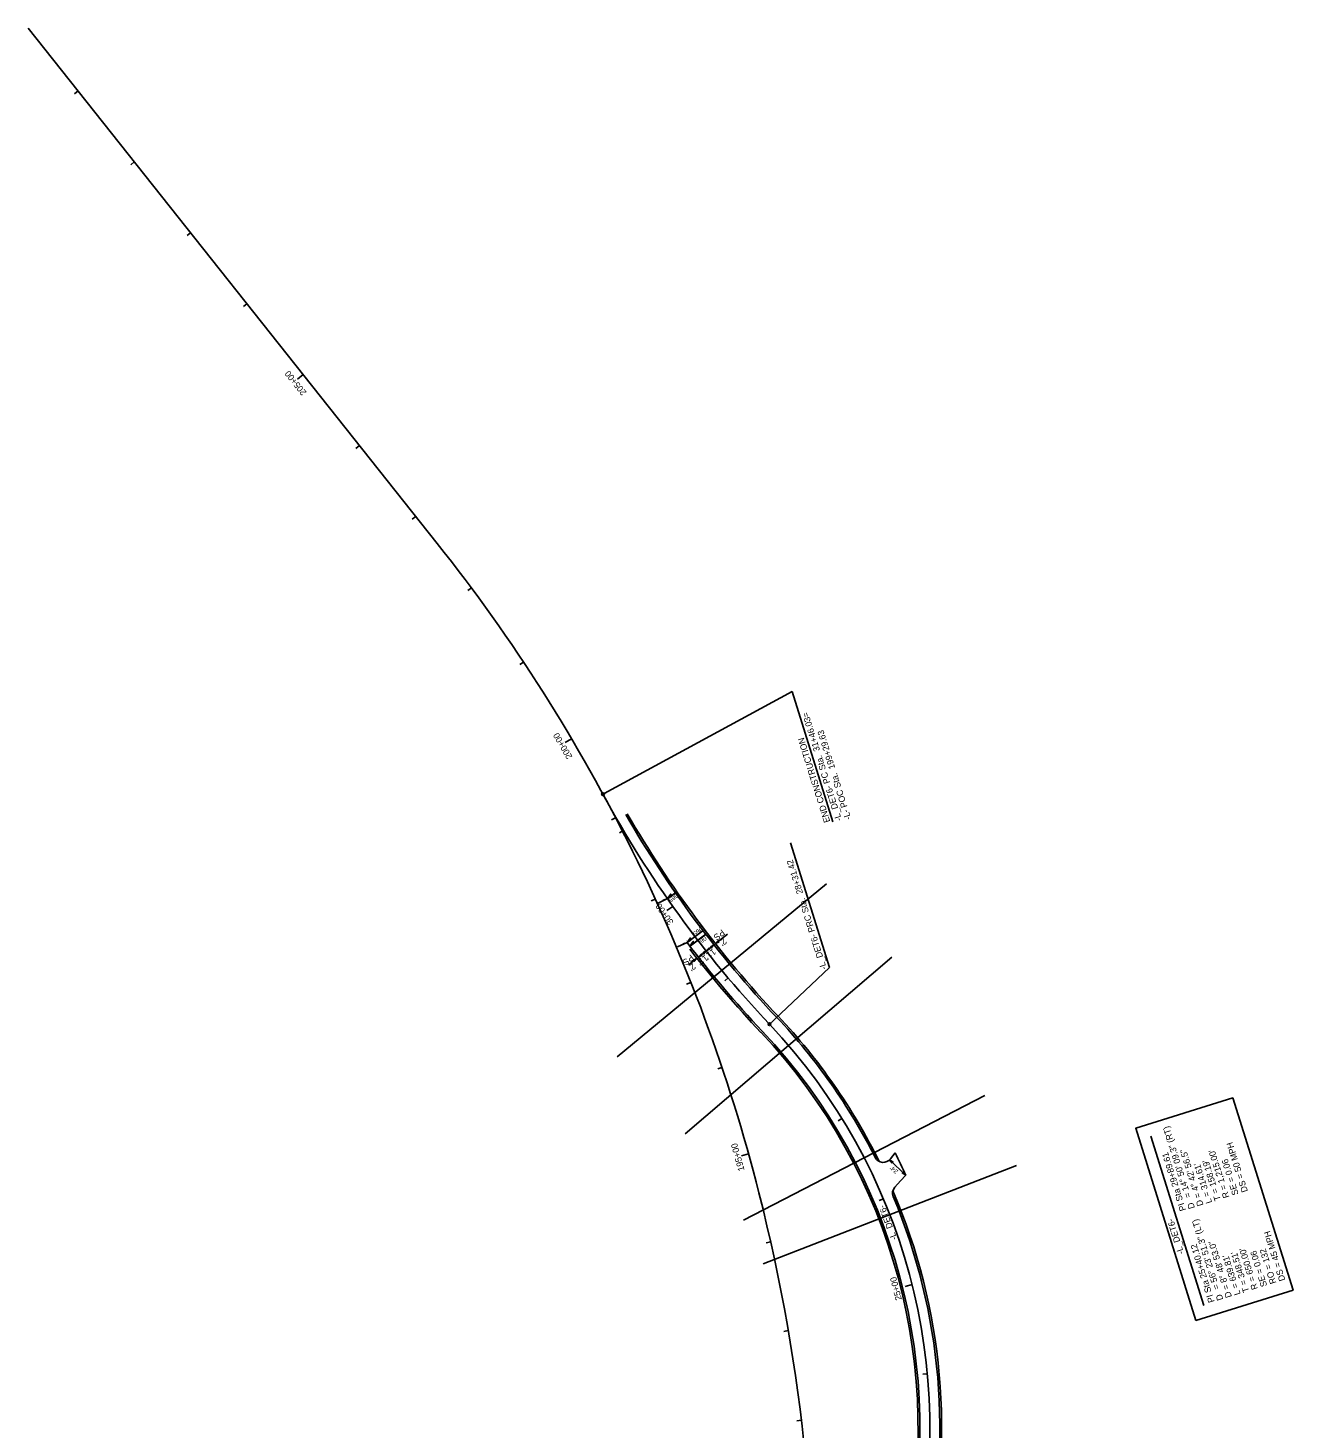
# Model space of a CAD drawing. Extents: x 473658 to 481584, y 489119 to 506230.
# Drawn here: x 473658 to 475055, y 504684 to 506230 of the extents above; entities that cross this region are included whole.
import ezdxf

# ---------------------------------------------------------------- set-up
doc = ezdxf.new("R2010")
doc.units = 0
for name, color, linetype in [('Exist Horizontal Alignment', 7, 'Continuous'), ('Prop Dimension', 7, 'Continuous'), ('Prop EOT', 7, 'Continuous'), ('Prop Grid Mask', 7, 'Continuous'), ('Prop Horizontal Alignment', 7, 'Continuous'), ('Prop Horizontal Alignment Curve and Spiral Data', 7, 'Continuous'), ('Prop Horizontal Alignment Station Label', 7, 'Continuous'), ('Prop Horizontal Alignment Tick Label', 7, 'Continuous'), ('Prop Horizontal Alignment Tick Large', 7, 'Continuous'), ('Prop Horizontal Alignment Tick Small', 7, 'Continuous'), ('Prop Paved Shoulder', 7, 'Continuous'), ('Prop Superelevation  Arrow CELL', 7, 'Continuous'), ('Prop Superelevation Label', 7, 'Continuous'), ('Scratch_Level_6', 7, 'Continuous')]:
    doc.layers.add(name, color=color, linetype=linetype)

msp = doc.modelspace()

# ---------------------------------------------------------------- linework, layer by layer
at = {"layer": 'Exist Horizontal Alignment'}
for points in [[(474611.9, 504976.5), (474609.2, 504980.2), (474613, 504977.6), (474612.1, 504977.4)], [(474624.2, 504966.7), (474626.9, 504963), (474623.1, 504965.5), (474624.1, 504965.7)]]:
    msp.add_lwpolyline(points, close=True, dxfattribs=at)
at = {"layer": 'Prop Dimension'}
for p, q in [((474430.1, 505229.2), (474416.9, 505218.8)), ((474415.3, 505217.5), (474398, 505203.9)), ((474396.5, 505202.7), (474387.2, 505195.4)), ((474626.9, 504963), (474609.2, 504980.2))]:
    msp.add_line(p, q, dxfattribs=at)
for points in [[(474410.7, 505212.9), (474406.7, 505210.7), (474409.7, 505214.1), (474409.8, 505213.2)], [(474411.3, 505215.3), (474415.3, 505217.5), (474412.3, 505214.1), (474412.2, 505215.1)], [(474420.9, 505220.9), (474416.9, 505218.8), (474419.9, 505222.2), (474420, 505221.2)], [(474392.5, 505200.5), (474396.5, 505202.7), (474393.4, 505199.2), (474393.4, 505200.2)], [(474402.1, 505206.1), (474398, 505203.9), (474401.1, 505207.3), (474401.1, 505206.3)], [(474402.7, 505208.5), (474406.7, 505210.7), (474403.6, 505207.3), (474403.6, 505208.3)]]:
    msp.add_lwpolyline(points, close=True, dxfattribs=at)
at = {"layer": 'Prop EOT'}
for p, q in [((474610.1, 504981.2), (474615.2, 504987.8)), ((474614.8, 504949.7), (474621, 504957)), ((474621, 504957), (474626.9, 504963))]:
    msp.add_line(p, q, dxfattribs=at)
for centre, radius, start, end in [((475360.5, 505963.2), 1204, 209.9929, 223.3134), ((475360.5, 505963.2), 1226, 217.3216, 223.3134), ((474003.6, 504683.9), 661, 26.8755, 43.3134), ((474003.6, 504683.9), 639, 346.9158, 43.3134), ((474602.1, 504987.2), 10, 206.8755, 322.9169), ((474003.6, 504683.9), 683, 24.1193, 26.4214), ((474622.4, 504943.2), 10, 139.5877, 202.7364), ((474003.6, 504683.9), 661, 346.9158, 22.7364)]:
    msp.add_arc(centre, radius, start, end, dxfattribs=at)
at = {"layer": 'Prop Grid Mask'}
msp.add_lwpolyline([(474947.5, 504802.7), (474881, 505015), (474988.1, 505048.5), (475054.7, 504836.2)], close=True, dxfattribs=at)
at = {"layer": 'Prop Horizontal Alignment'}
msp.add_line((474109.5, 505660.9), (473657.6, 506230), dxfattribs=at)
for centre, radius, start, end in [((472613.7, 504473.2), 1910, 14.2597, 38.4488), ((475360.5, 505963.2), 1215, 208.4775, 223.3134), ((474003.6, 504683.9), 650, 346.9158, 43.3134), ((472541, 504454.7), 1985, 356.9688, 14.2597)]:
    msp.add_arc(centre, radius, start, end, dxfattribs=at)
at = {"layer": 'Prop Horizontal Alignment Station Label'}
for p, q in [((474293.9, 505384.6), (474501.5, 505497.3)), ((474501.5, 505497.3), (474546.6, 505353.4)), ((474499.6, 505330.2), (474542.8, 505192.3)), ((474475.4, 505128.7), (474542.8, 505192.3)), ((474897.6, 505006.2), (474956.2, 504819.1))]:
    msp.add_line(p, q, dxfattribs=at)
for centre in [(474292.6, 505383.9), (474476.5, 505129.8)]:
    msp.add_circle(centre, 1.5, dxfattribs=at)
at = {"layer": 'Prop Horizontal Alignment Tick Large'}
for p, q in [((473961.5, 505847.2), (473955.3, 505842.2)), ((474257.9, 505445.1), (474251, 505441.1)), ((474369.7, 505260), (474363.2, 505255.4)), ((474453.4, 504986.5), (474445.7, 504984.3)), ((474634, 504842.2), (474626.2, 504840.3))]:
    msp.add_line(p, q, dxfattribs=at)
at = {"layer": 'Prop Horizontal Alignment Tick Small'}
for p, q in [((473712.8, 506160.5), (473708.9, 506157.4)), ((473775, 506082.2), (473771.1, 506079.1)), ((473837.2, 506003.9), (473833.3, 506000.7)), ((473899.3, 505925.5), (473895.4, 505922.4)), ((474023.7, 505768.9), (474019.8, 505765.8)), ((474085.9, 505690.6), (474082, 505687.5)), ((474147.3, 505611.7), (474143.3, 505608.7)), ((474204.8, 505529.8), (474200.6, 505527.1)), ((474306.5, 505357.7), (474302.1, 505355.4)), ((474315.3, 505343.9), (474311, 505341.3)), ((474350.5, 505267.9), (474345.9, 505265.9)), ((474430.9, 505181), (474427.1, 505177.7)), ((474389.7, 505176), (474385, 505174.1)), ((474497.5, 505106.4), (474493.7, 505103.1)), ((474424, 505082.1), (474419.3, 505080.5)), ((474556.4, 505025.7), (474552.2, 505023.1)), ((474602.3, 504936.9), (474597.7, 504935)), ((474477.8, 504889.5), (474472.9, 504888.4)), ((474497.2, 504791.4), (474492.3, 504790.6)), ((474650.8, 504743.7), (474645.8, 504743.3)), ((474511.7, 504692.5), (474506.7, 504691.9))]:
    msp.add_line(p, q, dxfattribs=at)
at = {"layer": 'Prop Paved Shoulder'}
for centre, radius, start, end in [((475360.5, 505963.2), 1202, 209.9929, 223.3134), ((475360.5, 505963.2), 1228, 217.6641, 223.3134), ((474003.6, 504683.9), 663, 26.3601, 43.3134), ((474003.6, 504683.9), 637, 346.9158, 43.3134), ((474003.6, 504683.9), 663, 346.9158, 23.2518)]:
    msp.add_arc(centre, radius, start, end, dxfattribs=at)
at = {"layer": 'Prop Superelevation  Arrow CELL'}
for points in [[(474363.8, 505268.5), (474367.5, 505273.6), (474367.6, 505271.1)], [(474385.6, 505219.9), (474389.1, 505225.1), (474389.3, 505222.7)], [(474388.6, 505215.9), (474392.2, 505221.2), (474392.3, 505218.7)]]:
    msp.add_lwpolyline(points, close=True, dxfattribs=at)
at = {"layer": 'Prop Superelevation Label'}
for p, q in [((474363.8, 505268.5), (474372.8, 505274.8)), ((474385.6, 505219.9), (474403.1, 505233.3)), ((474388.6, 505215.9), (474406.1, 505229.3))]:
    msp.add_line(p, q, dxfattribs=at)
at = {"layer": 'Scratch_Level_6'}
for p, q in [((474308.2, 505093.9), (474539.5, 505284.9)), ((474363.8, 505268.5), (474353.5, 505263.6)), ((474359.1, 505266.7), (474361.3, 505267.7)), ((474389.4, 505216.5), (474405.3, 505228.7)), ((474385.6, 505219.9), (474375, 505215.4)), ((474380.8, 505218.2), (474383, 505219.2)), ((474383.5, 505008.9), (474611.5, 505203.9)), ((474447.8, 504913.4), (474714.3, 505051)), ((474469.6, 504865), (474749.2, 504973.7))]:
    msp.add_line(p, q, dxfattribs=at)
for points in [[(474359.1, 505266.7), (474359.6, 505267.1), (474359.6, 505266.9)], [(474380.8, 505218.2), (474381.3, 505218.6), (474381.2, 505218.4)]]:
    msp.add_lwpolyline(points, close=True, dxfattribs=at)

# ---------------------------------------------------------------- texts
at = {"layer": 'Prop Dimension'}
for s, height, rotation, p in [('PS', 7, 218.2865, (474423.7, 505235)), ("11'", 7, 218.2865, (474414, 505213.8)), ("2'", 7, 218.2865, (474425.9, 505225.4)), ('PS', 7, 218.2865, (474389.5, 505207.3)), ("2'", 7, 218.2865, (474391.7, 505197.7)), ("11'", 7, 218.2865, (474405.4, 505207)), ("24'", 5, 135.7216, (474619, 504967.7))]:
    msp.add_text(s, height=height, rotation=rotation, dxfattribs=at).set_placement(p)
at = {"layer": 'Prop Horizontal Alignment Curve and Spiral Data'}
for s, p in [('= 14%%d 50\' 09.3" (RT)', (474942.2, 504939.2)), ('DS = 50 MPH', (475004.9, 504945.4)), ('PI Sta 29+89.61', (474936.6, 504924.7)), ('D = 4%%d 42\' 56.5"', (474955.9, 504930.1)), ("R = 1,215.00'", (474984.5, 504939)), ('SE = 0.06', (474994.7, 504942.2)), ("L = 314.61'", (474965.4, 504933)), ("T = 158.19'", (474975, 504936)), ('D', (474946.4, 504927.1)), ('= 56%%d 23\' 51.3" (LT)', (474973.7, 504838)), ('PI Sta 25+40.12', (474968.1, 504823.5)), ('D = 8%%d 48\' 53.0"', (474987.3, 504828.9)), ('DS = 45 MPH', (475046.3, 504847.3)), ("L = 639.81'", (474996.9, 504831.8)), ("T = 348.51'", (475006.4, 504834.8)), ("R = 650.00'", (475016, 504837.8)), ('SE = 0.06', (475026.2, 504841)), ('RO = 132', (475036.3, 504844.2)), ('D', (474977.8, 504825.9))]:
    msp.add_text(s, height=7, rotation=107.3948, dxfattribs=at).set_placement(p)
at = {"layer": 'Prop Horizontal Alignment Station Label'}
for s, p in [('-L_DET6- PC Sta.  31+46.03=', (474556.5, 505355.4)), ('END CONSTRUCTION', (474543.6, 505353.7)), ('-L- POC Sta.  199+29.63', (474566.8, 505356.7)), ('-L_DET6- PRC Sta.  28+31.42', (474539.8, 505191.3)), ('-L_DET6-', (474934.3, 504877))]:
    msp.add_text(s, height=7, rotation=107.3948, dxfattribs=at).set_placement(p)
at = {"layer": 'Prop Horizontal Alignment Tick Label'}
for s, rotation, p in [('205+00', 128.4488, (473965.6, 505827.7)), ('200+00', 120.5884, (474259.1, 505425.3)), ('30+00', 125.3638, (474371, 505242.7)), ('195+00', 105.5895, (474449, 504968.7)), ('-L_DET6-', 110.3021, (474617.6, 504892.8)), ('25+00', 104.0993, (474622.7, 504825.8))]:
    msp.add_text(s, height=7, rotation=rotation, dxfattribs=at).set_placement(p)
at = {"layer": 'Prop Superelevation Label'}
for s, rotation, p in [('.065', 214.8753, (474375.3, 505275.9)), ('.065', 217.3216, (474402.1, 505238.9)), ('.06', 217.5575, (474406.2, 505228.8))]:
    msp.add_text(s, height=5, rotation=rotation, dxfattribs=at).set_placement(p)
at = {"layer": 'Scratch_Level_6'}
for s, rotation, p in [('1616.55', 119.9458, (474353.9, 505263.9)), ("11.40'", 205.2436, (474360, 505266.2)), ('.062', 205.2436, (474360.7, 505268.2)), ('1617.26', 119.9458, (474364.3, 505268.8)), ('1614.78', 117.6108, (474375.4, 505215.7)), ("11.50'", 202.9087, (474381.6, 505217.7)), ('.065', 202.9087, (474382.4, 505219.7)), ('1615.53', 117.6108, (474386, 505220.2))]:
    msp.add_text(s, height=0.5, rotation=rotation, dxfattribs=at).set_placement(p)

doc.saveas('drawing.dxf')
